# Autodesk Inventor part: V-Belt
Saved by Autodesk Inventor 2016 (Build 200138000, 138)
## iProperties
Created: 2015-03
Part Number: V-Belt
Material: Rubber
Document SubType Name: Modeling
Designer: Uglješa
Density: 0.93 g/cm^3
Appearance: Rubber - Black - Version 1.1
CustomPartVersion: 1
Author: Uglješa
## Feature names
1. Belt
## Parameters: da_Alfa = 40 deg, da_H = 6 mm, da_Bw = 8.5 mm, da_Hw = 2.49859 mm, d0 = 8.5 mm, d1 = 2.49859 mm, d2 = 40 deg, d3 = 6 mm, d4 = 0, d5 = 0, d6 = 0, d7 = 0, d8 = 0, d9 = 0
